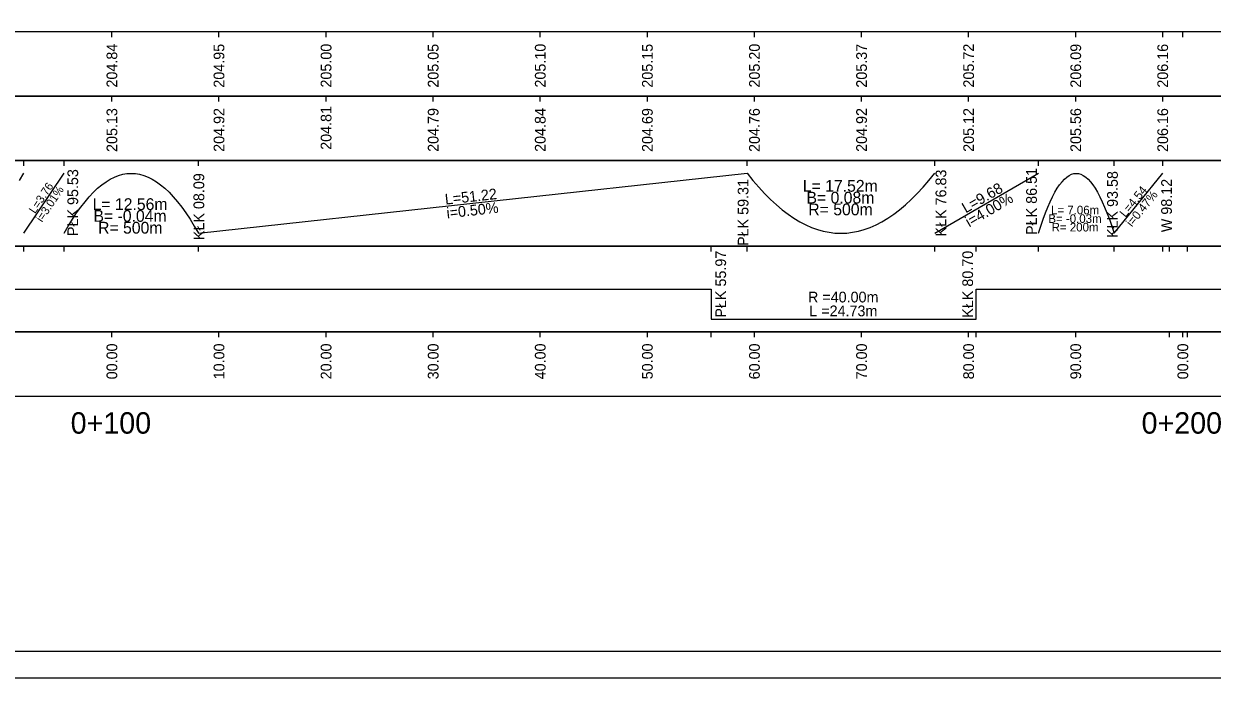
# Model space of a CAD drawing. Extents: x 6513080 to 6513380, y 6022307 to 6022469.
# Drawn here: x 6513209.5 to 6513320.4, y 6022306.7 to 6022367.8 of the extents above; entities that cross this region are included whole.
import ezdxf

# ---------------------------------------------------------------- set-up
doc = ezdxf.new("R2010")
doc.units = 0
for name, color, linetype in [('1', 7, 'Continuous'), ('31', 7, 'Continuous'), ('42', 7, 'Continuous'), ('54', 7, 'Continuous'), ('Level 20', 7, 'Continuous'), ('maxp_ramka_2', 7, 'Continuous')]:
    doc.layers.add(name, color=color, linetype=linetype)

msp = doc.modelspace()

# ---------------------------------------------------------------- linework, layer by layer
for points in [[(6513209.08, 6022353.18), (6513209.47, 6022353.86)], [(6513209.47, 6022348.26), (6513213.23, 6022353.86)], [(6513213.23, 6022348.26), (6513213.62, 6022348.94), (6513214.01, 6022349.57), (6513214.41, 6022350.16), (6513214.8, 6022350.71), (6513215.19, 6022351.21), (6513215.58, 6022351.67), (6513215.97, 6022352.09), (6513216.37, 6022352.46), (6513216.76, 6022352.79), (6513217.15, 6022353.07), (6513217.54, 6022353.31), (6513217.94, 6022353.51), (6513218.33, 6022353.66), (6513218.72, 6022353.77), (6513219.11, 6022353.84), (6513219.9, 6022353.84), (6513220.29, 6022353.77), (6513220.68, 6022353.66), (6513221.08, 6022353.51), (6513221.47, 6022353.31), (6513221.86, 6022353.07), (6513222.25, 6022352.79), (6513222.65, 6022352.46), (6513223.04, 6022352.09), (6513223.43, 6022351.67), (6513223.82, 6022351.21), (6513224.22, 6022350.71), (6513224.61, 6022350.16), (6513225, 6022349.57), (6513225.39, 6022348.94), (6513225.79, 6022348.26)], [(6513225.79, 6022348.26), (6513277.01, 6022353.86)], [(6513277.01, 6022353.86), (6513277.56, 6022353.18), (6513278.11, 6022352.55), (6513278.65, 6022351.96), (6513279.2, 6022351.41), (6513279.75, 6022350.91), (6513280.3, 6022350.45), (6513280.84, 6022350.03), (6513281.39, 6022349.66), (6513281.94, 6022349.33), (6513282.49, 6022349.05), (6513283.03, 6022348.81), (6513283.58, 6022348.61), (6513284.13, 6022348.46), (6513284.68, 6022348.35), (6513285.22, 6022348.28), (6513286.32, 6022348.28), (6513286.87, 6022348.35), (6513287.41, 6022348.46), (6513287.96, 6022348.61), (6513288.51, 6022348.81), (6513289.06, 6022349.05), (6513289.6, 6022349.33), (6513290.15, 6022349.66), (6513290.7, 6022350.03), (6513291.25, 6022350.45), (6513291.79, 6022350.91), (6513292.34, 6022351.41), (6513292.89, 6022351.96), (6513293.44, 6022352.55), (6513293.98, 6022353.18), (6513294.53, 6022353.86)], [(6513294.53, 6022348.26), (6513304.21, 6022353.86)], [(6513304.21, 6022348.26), (6513304.43, 6022348.94), (6513304.65, 6022349.57), (6513304.88, 6022350.16), (6513305.1, 6022350.71), (6513305.32, 6022351.21), (6513305.54, 6022351.67), (6513305.76, 6022352.09), (6513305.98, 6022352.46), (6513306.2, 6022352.79), (6513306.42, 6022353.07), (6513306.64, 6022353.31), (6513306.86, 6022353.51), (6513307.08, 6022353.66), (6513307.3, 6022353.77), (6513307.52, 6022353.84), (6513307.97, 6022353.84), (6513308.19, 6022353.77), (6513308.41, 6022353.66), (6513308.63, 6022353.51), (6513308.85, 6022353.31), (6513309.07, 6022353.07), (6513309.29, 6022352.79), (6513309.51, 6022352.46), (6513309.73, 6022352.09), (6513309.95, 6022351.67), (6513310.17, 6022351.21), (6513310.39, 6022350.71), (6513310.61, 6022350.16), (6513310.84, 6022349.57), (6513311.06, 6022348.94), (6513311.28, 6022348.26)], [(6513311.28, 6022348.26), (6513315.82, 6022353.86)], [(6513117.7, 6022343.06), (6513133.93, 6022343.06), (6513133.93, 6022340.26), (6513136.15, 6022340.26), (6513136.15, 6022343.06), (6513152.08, 6022343.06), (6513152.08, 6022345.86), (6513157.31, 6022345.86), (6513157.31, 6022343.06), (6513185.95, 6022343.06), (6513185.95, 6022340.26), (6513207.39, 6022340.26), (6513207.39, 6022343.06), (6513273.67, 6022343.06), (6513273.67, 6022340.26), (6513298.4, 6022340.26), (6513298.4, 6022343.06), (6513316.46, 6022343.06), (6513316.46, 6022343.06), (6513318.13, 6022343.06), (6513318.13, 6022343.06), (6513323.11, 6022343.06)]]:
    msp.add_lwpolyline(points)
at = {"layer": '54'}
for points in [[(6513117.7, 6022361.06), (6513327.7, 6022361.06), (6513327.7, 6022367.06), (6513117.7, 6022367.06)], [(6513117.7, 6022355.06), (6513327.7, 6022355.06), (6513327.7, 6022361.06), (6513117.7, 6022361.06)], [(6513117.7, 6022347.06), (6513327.7, 6022347.06), (6513327.7, 6022355.06), (6513117.7, 6022355.06)], [(6513117.7, 6022339.06), (6513327.7, 6022339.06), (6513327.7, 6022347.06), (6513117.7, 6022347.06)], [(6513117.7, 6022333.06), (6513327.7, 6022333.06), (6513327.7, 6022339.06), (6513117.7, 6022339.06)]]:
    msp.add_lwpolyline(points, close=True, dxfattribs=at)
for points in [[(6513217.7, 6022366.56), (6513217.7, 6022367.06)], [(6513227.7, 6022366.56), (6513227.7, 6022367.06)], [(6513237.7, 6022366.56), (6513237.7, 6022367.06)], [(6513247.7, 6022366.56), (6513247.7, 6022367.06)], [(6513257.7, 6022366.56), (6513257.7, 6022367.06)], [(6513267.7, 6022366.56), (6513267.7, 6022367.06)], [(6513277.7, 6022366.56), (6513277.7, 6022367.06)], [(6513287.7, 6022366.56), (6513287.7, 6022367.06)], [(6513297.7, 6022366.56), (6513297.7, 6022367.06)], [(6513307.7, 6022366.56), (6513307.7, 6022367.06)], [(6513315.82, 6022366.56), (6513315.82, 6022367.06)], [(6513317.7, 6022366.56), (6513317.7, 6022367.06)], [(6513217.7, 6022360.56), (6513217.7, 6022361.06)], [(6513227.7, 6022360.56), (6513227.7, 6022361.06)], [(6513237.7, 6022360.56), (6513237.7, 6022361.06)], [(6513247.7, 6022360.56), (6513247.7, 6022361.06)], [(6513257.7, 6022360.56), (6513257.7, 6022361.06)], [(6513267.7, 6022360.56), (6513267.7, 6022361.06)], [(6513277.7, 6022360.56), (6513277.7, 6022361.06)], [(6513287.7, 6022360.56), (6513287.7, 6022361.06)], [(6513297.7, 6022360.56), (6513297.7, 6022361.06)], [(6513307.7, 6022360.56), (6513307.7, 6022361.06)], [(6513315.82, 6022360.56), (6513315.82, 6022361.06)], [(6513209.47, 6022354.56), (6513209.47, 6022355.06)], [(6513213.23, 6022354.56), (6513213.23, 6022355.06)], [(6513225.79, 6022354.56), (6513225.79, 6022355.06)], [(6513277.01, 6022354.56), (6513277.01, 6022355.06)], [(6513294.53, 6022354.56), (6513294.53, 6022355.06)], [(6513304.21, 6022354.56), (6513304.21, 6022355.06)], [(6513311.28, 6022354.56), (6513311.28, 6022355.06)], [(6513315.82, 6022354.56), (6513315.82, 6022355.06)], [(6513209.47, 6022346.56), (6513209.47, 6022347.06)], [(6513213.23, 6022346.56), (6513213.23, 6022347.06)], [(6513225.79, 6022346.56), (6513225.79, 6022347.06)], [(6513273.67, 6022346.56), (6513273.67, 6022347.06)], [(6513277.01, 6022346.56), (6513277.01, 6022347.06)], [(6513294.53, 6022346.56), (6513294.53, 6022347.06)], [(6513298.4, 6022346.56), (6513298.4, 6022347.06)], [(6513304.21, 6022346.56), (6513304.21, 6022347.06)], [(6513311.28, 6022346.56), (6513311.28, 6022347.06)], [(6513315.82, 6022346.56), (6513315.82, 6022347.06)], [(6513316.46, 6022346.56), (6513316.46, 6022347.06)], [(6513318.13, 6022346.56), (6513318.13, 6022347.06)], [(6513217.7, 6022338.56), (6513217.7, 6022339.06)], [(6513227.7, 6022338.56), (6513227.7, 6022339.06)], [(6513237.7, 6022338.56), (6513237.7, 6022339.06)], [(6513247.7, 6022338.56), (6513247.7, 6022339.06)], [(6513257.7, 6022338.56), (6513257.7, 6022339.06)], [(6513267.7, 6022338.56), (6513267.7, 6022339.06)], [(6513273.67, 6022338.56), (6513273.67, 6022339.06)], [(6513277.7, 6022338.56), (6513277.7, 6022339.06)], [(6513287.7, 6022338.56), (6513287.7, 6022339.06)], [(6513297.7, 6022338.56), (6513297.7, 6022339.06)], [(6513298.4, 6022338.56), (6513298.4, 6022339.06)], [(6513307.7, 6022338.56), (6513307.7, 6022339.06)], [(6513316.46, 6022338.56), (6513316.46, 6022339.06)], [(6513317.7, 6022338.56), (6513317.7, 6022339.06)], [(6513318.13, 6022338.56), (6513318.13, 6022339.06)]]:
    msp.add_lwpolyline(points, dxfattribs=at)
at = {"layer": 'maxp_ramka_2'}
for points in [[(6513079.9, 6022455.24), (6513379.9, 6022455.24), (6513379.9, 6022306.74), (6513079.9, 6022306.74)], [(6513092.4, 6022309.24), (6513092.4, 6022452.74), (6513377.4, 6022452.74), (6513377.4, 6022309.24)]]:
    msp.add_lwpolyline(points, close=True, dxfattribs=at)

# ---------------------------------------------------------------- texts
at = {"layer": '1'}
for s, p in [('205.13', (6513218.2, 6022355.85)), ('204.92', (6513228.2, 6022355.86)), ('204.81', (6513238.2, 6022356.05)), ('204.79', (6513248.2, 6022355.86)), ('204.84', (6513258.2, 6022355.86)), ('204.69', (6513268.2, 6022355.85)), ('204.76', (6513278.2, 6022355.85)), ('204.92', (6513288.2, 6022355.86)), ('205.12', (6513298.2, 6022355.86)), ('205.56', (6513308.2, 6022355.85)), ('206.16', (6513316.32, 6022355.85)), ('PŁK 95.53', (6513214.55, 6022348)), ('KŁK 76.83', (6513295.61, 6022347.96)), ('PŁK 86.51', (6513304.07, 6022348.11)), ('KŁK 93.58', (6513311.63, 6022347.82)), ('KŁK 08.09', (6513226.32, 6022347.62)), ('PŁK 59.31', (6513277.14, 6022347.08)), ('W 98.12', (6513316.68, 6022348.36))]:
    msp.add_text(s, height=1, rotation=90, dxfattribs=at).set_placement(p)
for s, p in [('0+100', (6513213.85, 6022329.56)), ('0+200', (6513313.85, 6022329.56))]:
    msp.add_text(s, height=2, dxfattribs=at).set_placement(p)
at = {"layer": '31'}
for s, p in [('204.84', (6513218.2, 6022361.86)), ('204.95', (6513228.2, 6022361.85)), ('205.00', (6513238.2, 6022361.86)), ('205.05', (6513248.2, 6022361.85)), ('205.10', (6513258.2, 6022361.86)), ('205.15', (6513268.2, 6022361.85)), ('205.20', (6513278.2, 6022361.86)), ('205.37', (6513288.2, 6022361.85)), ('205.72', (6513298.2, 6022361.86)), ('206.09', (6513308.2, 6022361.85)), ('206.16', (6513316.32, 6022361.85))]:
    msp.add_text(s, height=1, rotation=90, dxfattribs=at).set_placement(p)
at = {"layer": '42'}
for s, height, p in [('L= 17.52m', 1.1, (6513282.22, 6022352.14)), ('B= 0.08m', 1.1, (6513282.56, 6022351.04)), ('L= 12.56m', 1.1, (6513215.9, 6022350.43)), ('R= 500m', 1.1, (6513282.73, 6022349.94)), ('L= 7.06m', 0.802, (6513305.39, 6022350.03)), ('B= -0.04m', 1.1, (6513215.98, 6022349.33)), ('B= -0.03m', 0.802, (6513305.14, 6022349.23)), ('R= 500m', 1.1, (6513216.41, 6022348.23)), ('R= 200m', 0.802, (6513305.45, 6022348.43))]:
    msp.add_text(s, height=height, dxfattribs=at).set_placement(p)
at = {"layer": '54'}
for s, p in [('PŁK 55.97', (6513275.05, 6022340.39)), ('KŁK 80.70', (6513298.11, 6022340.38)), ('00.00', (6513218.2, 6022334.63)), ('10.00', (6513228.2, 6022334.63)), ('20.00', (6513238.2, 6022334.63)), ('30.00', (6513248.2, 6022334.63)), ('40.00', (6513258.2, 6022334.63)), ('50.00', (6513268.2, 6022334.63)), ('60.00', (6513278.2, 6022334.63)), ('70.00', (6513288.2, 6022334.63)), ('80.00', (6513298.2, 6022334.63)), ('90.00', (6513308.2, 6022334.63)), ('00.00', (6513318.2, 6022334.63))]:
    msp.add_text(s, height=1, rotation=90, dxfattribs=at).set_placement(p)
for s, p in [('R =40.00m', (6513282.7, 6022341.81)), ('L =24.73m', (6513282.82, 6022340.52))]:
    msp.add_text(s, height=1, dxfattribs=at).set_placement(p)
at = {"layer": 'Level 20'}
for s, height, rotation, p in [('L=3.76', 0.767, 56.1423, (6513210.52, 6022350.04)), ('L=9.68', 1, 30.0483, (6513297.43, 6022350.11)), ('i=3.01%', 0.767, 56.1423, (6513211.18, 6022349.24)), ('L=51.22', 1, 6.239, (6513248.85, 6022350.93)), ('i=4.00%', 1, 30.0483, (6513297.75, 6022348.8)), ('L=4.54', 0.802, 50.9514, (6513312.34, 6022349.69)), ('i=0.47%', 0.802, 50.9514, (6513312.95, 6022348.8)), ('i=0.50%', 1, 6.239, (6513249, 6022349.65))]:
    msp.add_text(s, height=height, rotation=rotation, dxfattribs=at).set_placement(p)

doc.saveas('drawing.dxf')
